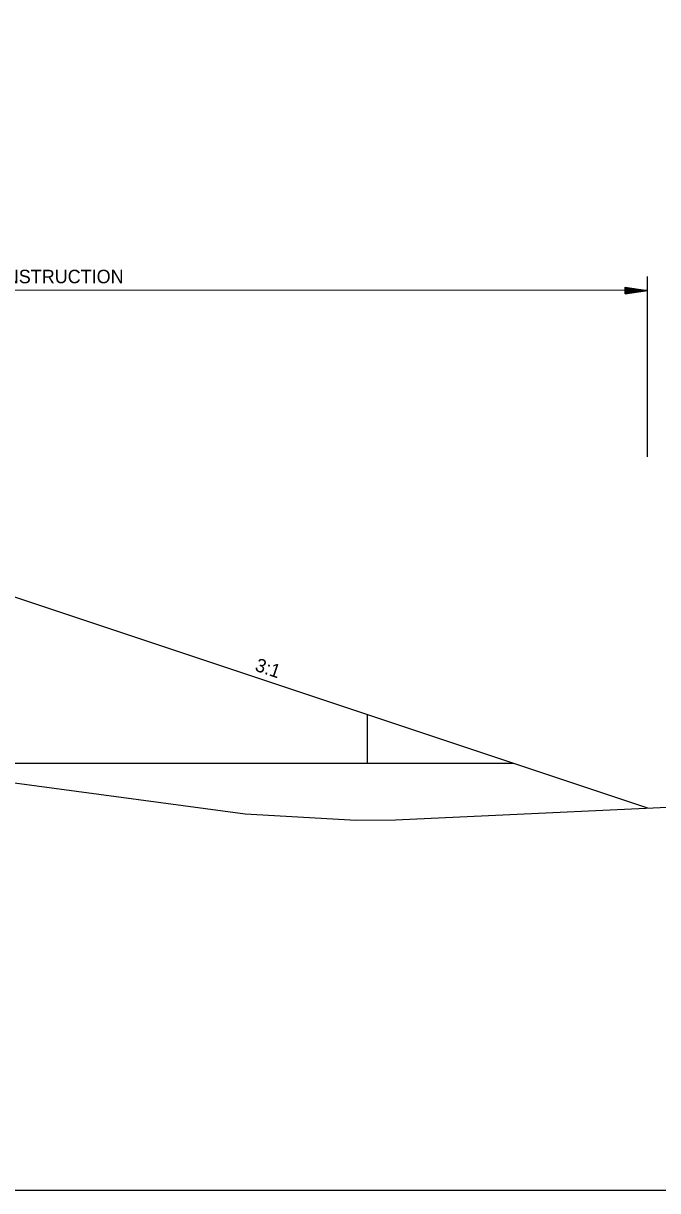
# Model space of a CAD drawing. Extents: x 2829243 to 2838161, y 467639 to 474695.
# Drawn here: x 2830653 to 2830937, y 468471 to 468992 of the extents above; entities that cross this region are included whole.
import ezdxf

# ---------------------------------------------------------------- set-up
doc = ezdxf.new("R2010")
doc.units = 0
for name, color, linetype in [('Default', 7, 'Continuous'), ('R_Dimension', 7, 'Continuous'), ('R_Exist Surface', 7, 'Continuous'), ('R_Fin Surface', 7, 'Continuous'), ('R_Water', 7, 'Continuous'), ('R_Xsect Slope', 7, 'Continuous')]:
    doc.layers.add(name, color=color, linetype=linetype)

msp = doc.modelspace()

# ---------------------------------------------------------------- linework, layer by layer
at = {"layer": 'Default'}
msp.add_lwpolyline([(2829486.2, 470265.93), (2831121.84, 470265.93), (2831121.84, 468471.1), (2829486.2, 468471.1)], close=True, dxfattribs=at)
at = {"layer": 'R_Dimension'}
for p, q in [((2830932.13, 468798.6), (2830932.13, 468879.1)), ((2830932.13, 468872.89), (2830370.56, 468873.1)), ((2830922.13, 468874.39), (2830932.13, 468872.89)), ((2830922.13, 468871.39), (2830922.13, 468874.39)), ((2830922.13, 468874.14), (2830930.46, 468872.89)), ((2830922.13, 468873.89), (2830928.74, 468872.89)), ((2830922.13, 468873.64), (2830927.07, 468872.89)), ((2830922.13, 468873.38), (2830925.38, 468872.89)), ((2830922.13, 468873.13), (2830923.71, 468872.89)), ((2830922.13, 468871.39), (2830932.13, 468872.89)), ((2830922.13, 468872.41), (2830925.38, 468872.89)), ((2830922.13, 468871.9), (2830928.74, 468872.89)), ((2830922.13, 468871.64), (2830930.46, 468872.89)), ((2830922.13, 468872.15), (2830927.07, 468872.89)), ((2830922.13, 468872.66), (2830923.71, 468872.89))]:
    msp.add_line(p, q, dxfattribs=at)
at = {"layer": 'R_Exist Surface'}
msp.add_lwpolyline([(2830370.56, 468762.33), (2830445.65, 468760.26), (2830472.01, 468759.49), (2830501.37, 468758.49), (2830561.18, 468754.86), (2830564.55, 468753.49), (2830572.96, 468753.39), (2830593.41, 468692.09), (2830602.55, 468663.74), (2830610.47, 468660.13), (2830611.63, 468658.15), (2830752.48, 468639.25), (2830801.98, 468636.51), (2830819.56, 468636.66), (2830979.28, 468644.11), (2830991.76, 468643.84), (2831056.78, 468664.13), (2831065.2, 468667.65)], dxfattribs=at)
at = {"layer": 'R_Fin Surface'}
msp.add_lwpolyline([(2830535.45, 468762.79), (2830635.45, 468740.8), (2830932.13, 468641.91)], dxfattribs=at)
at = {"layer": 'R_Water'}
for p, q in [((2830806.91, 468683.65), (2830806.91, 468662.17)), ((2830645.45, 468661.86), (2830872.27, 468661.86))]:
    msp.add_line(p, q, dxfattribs=at)

# ---------------------------------------------------------------- texts
at = {"layer": 'R_Dimension'}
msp.add_text('STAGE 3 CONSTRUCTION', height=6, dxfattribs=at).set_placement((2830597.42, 468876.1))
at = {"layer": 'R_Xsect Slope'}
msp.add_text('3:1', height=6, rotation=341.5651, dxfattribs=at).set_placement((2830756.45, 468703.26))

doc.saveas('drawing.dxf')
